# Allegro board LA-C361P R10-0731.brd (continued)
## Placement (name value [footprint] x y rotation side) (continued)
PR268  0_0402_5%  [R_0402]  28.27 101.01 180 bottom
PR269  100K_0402_5%  [R_0402]  29.68 1.71 180 top
PR270  0_0402_5%  [R_0402]  9.27 16.65 0 bottom
PR271  100K_0402_1%  [R_0402]  29.41 25.15 180 top
PR272  100K_0402_1%  [R_0402]  29.34 24.25 270 top
PR273  16.5K_0402_1%  [R_0402]  17.65 20.07 0 bottom
PR274  100K_0402_1%  [R_0402]  23.31 10.22 90 top
PR275  100K_0402_1%  [R_0402]  34.6 31.94 0 top
PR276  2K_0402_1%  [R_0402]  34.57 33.85 180 top
PR277  0_0402_5%  [R_0402]  31.1 30.07 270 top
PR278  100K_0402_1%  [R_0402]  18.09 22.49 0 top
PR279  0_0402_5%  [R_0402]  19 23.5 180 top
PR280  0_0402_5%  [R_0402]  19.89 8.39 180 top
PR281  0_0402_5%  [R_0402]  33.71 32.42 270 top
PR282  100K_0402_5%  [R_0402]  10.21 11.57 0 top
PR283  100K_0402_5%  [R_0402]  8.5 10.04 0 top
PR287  0_0402_5%  [R_0402]  20.26 2.63 270 top
PR290  0_0402_5%  [R_0402]  20.31 30.36 0 bottom
PR291  0_0402_5%  [R_0402]  23 30.36 180 bottom
PR292  100K_0402_5%  [R_0402]  17.92 1.66 180 top
PR299  100K_0402_5%  [R_0402]  28.45 6.35 90 top
PR300  0.01_1206_1%  [R_1206_4P-D]  55.02 9.1 270 bottom
PR301  0_0402_5%  [R0402_0OHM]  52.57 11.1 90 top
PR302  0_0402_5%  [R0402_0OHM]  51.69 11.1 90 top
PR303  4.02K_0402_1%  [R_0402]  54.17 11.76 90 top
PR304  10_1206_5%  [R_1206]  51.12 15.06 270 bottom
PR305  294K_0402_1%  [R_0402]  55.77 12.67 270 bottom
PR306  0_0402_5%  [R0402_0OHM]  60.26 17.48 180 top
PR307  2.2_0603_5%  [R_0603]  50.8 17.53 180 top
PR308  59K_0402_1%  [R_0402]  55.88 14.54 90 bottom
PR309  0_0402_5%  [R0402_0OHM]  60.26 18.37 180 top
PR310  0.01_2512_1%  [R_2512_4P]  40.92 23.57 90 bottom
PR311  100K_0402_1%  [R_0402]  54.9 11.76 90 bottom
PR312  0_0402_5%  [R0402_0OHM]  54.04 11.76 90 bottom
PR313  4.7_1206_5%  [R_1206]  33.08 4.14 0 top
PR314  0_0402_5%  [R0402_0OHM]  56.9 11.76 90 top
PR315  100_0402_1%  [R_0402]  60.26 16.52 180 top
PR316  150K_0402_1%  [R_0402]  55.12 12.65 270 top
PR317  0_0402_5%  [R0402_0OHM]  60.28 14.74 180 top
PR318  10K_0402_1%  [R_0402]  52.39 21.34 90 top
PR319  4.02K_0402_1%  [R_0402]  55.18 21.22 90 top
PR320  10_0603_1%  [R_0603]  56.26 21.22 90 bottom
PR321  1K_0402_1%  [R_0402]  57.34 22.42 270 top
PR322  0_0402_5%  [R0402_0OHM]  58.23 22.42 270 top
PR323  121K_0402_1%  [R_0402]  56.64 19.33 270 bottom
PR324  0_0402_5%  [R0402_0OHM]  60.28 15.63 180 top
PR325  10K_0402_1%  [R_0402]  57.8 16.52 180 bottom
PR326  2.2K_0402_5%  [R_0402]  346.97 26.3 270 top
PR327  100K_0402_5%  [R_0402]  58.85 10.6 0 bottom
PR399  0_0402_5%  [R_0402]  52.77 11.74 90 bottom
PR400  0_0402_5%  [R0402_0OHM]  348.88 21.98 180 bottom
PR401  68.1K_0402_1%  [R_0402]  348.87 22.87 180 top
PR402  154K_0402_1%  [R_0402]  348.03 18.93 0 top
PR403  100K_0402_1%  [R_0402]  348.87 21.98 180 top
PR404  100K_0402_1%  [R_0402]  348.03 19.82 0 top
PR405  16.9K_0402_1%  [R_0402]  346.97 24.41 270 top
PR406  10.2K_0402_1%  [R_0402]  348.03 18.04 0 top
PR407  0_0402_5%  [R0402_0OHM]  345.12 24.41 270 top
PR408  0_0402_5%  [R0402_0OHM]  346.08 24.41 270 top
PR409  0_0402_5%  [R0402_0OHM]  347.98 17.14 90 bottom
PR410  200_0402_1%  [R_0402]  348.03 17.09 0 top
PR411  2.2_0603_5%  [R_0603]  342.27 24.08 0 top
PR412  2.2_0603_5%  [R_0603]  341.89 17.22 0 top
PR413  4.7_1206_5%  [R_1206]  337.69 29.47 90 top
PR414  4.7_1206_5%  [R_1206]  339.28 10.68 90 top
PR415  0_0402_5%  [R0402_0OHM]  340.58 21.97 180 top
PR428  100K_0402_1%  [R_0402]  345.12 24.41 270 bottom
PR500  0_0402_5%  [R0402_0OHM]  130.65 3.2 270 bottom
PR501  1M_0402_1%  [R_0402]  130.68 3.18 270 top
PR502  4.7_1206_5%  [R_1206]  126.68 8.33 0 bottom
PR503  0_0402_5%  [R0402_0OHM]  133.87 5.98 180 top
PR504  90.9K_0402_1%  [R_0402]  134.76 2.16 90 top
PR508  133K_0402_1%  [R_0402]  135.68 3.06 270 top
PR510  0_0402_5%  [R_0402]  132.46 2.26 90 top
PR512  0_0402_5%  [R_0402]  133.33 2.97 270 bottom
PR600  2.2_0603_5%  [R_0603]  283.15 28.65 0 bottom
PR601  3.57K_0402_1%  [R_0402]  288.99 26.49 180 bottom
PR602  4.7_1206_5%  [R_1206]  269.43 26.87 180 bottom
PR603  5.1_0603_5%  [R_0603]  289.54 25.23 90 top
PR604  16.2K_0402_1%  [R_0402]  291.85 31.19 90 top
PR605  1M_0402_1%  [R_0402]  292.75 27.19 180 bottom
PR606  0_0402_5%  [R0402_0OHM]  292.75 28.46 180 bottom
PR607  27K_0402_1%  [R_0402]  292.8 31.19 90 bottom
PR608  0_0402_5%  [R0402_0OHM]  292.75 29.35 180 bottom
PR609  100K_0402_5%  [R_0402]  292.75 26.3 180 bottom
PR610  0_0402_5%  [R_0402]  291.83 30.23 0 top
PR700  210K_0402_1%  [R_0402]  247.65 48.46 90 top
PR701  100K_0402_1%  [R_0402]  247.65 51.22 270 top
PR702  10_1206_5%  [R_1206]  236.91 51.96 0 top
PR703  5.1_0603_5%  [R_0603]  243.08 54.43 90 top
PR704  210K_0402_1%  [R_0402]  248.55 53.13 180 top
PR705  0_0402_5%  [R0402_0OHM]  248.55 52.16 180 top
PR800  0_0402_5%  [R0402_0OHM]  109.92 64.51 90 bottom
PR801  1M_0402_1%  [R_0402]  109.03 64.51 90 bottom
PR802  4.7_1206_5%  [R_1206]  114.17 57.67 180 bottom
PR803  0_0603_5%  [R0603_0OHM]  107.19 62.11 270 top
PR804  36.5K_0402_1%  [R_0402]  107.13 64.51 90 bottom
PR806  62K_0402_1%  [R_0402]  105.28 64.51 90 top
PR808  0_0402_5%  [R0402_0OHM]  171.69 70.68 270 top
PR809  0_0402_5%  [R0402_0OHM]  170.74 70.68 270 top
PR810  100_0402_1%  [R_0402]  170.74 72.46 270 top
PR811  0_0402_5%  [R_0402]  108.08 65.43 270 bottom
PR812  0_0402_5%  [R0402_0OHM]  107.13 64.51 90 top
PR813  100_0402_1%  [R_0402]  171.69 72.46 270 top
PR900  0_0402_5%  [R_0402]  221.35 53.73 0 top
PR901  1M_0402_1%  [R_0402]  220.16 54.17 90 bottom
PR902  4.7_1206_5%  [R_1206]  217.17 54.68 180 top
PR903  0_0603_5%  [R0603_0OHM]  220.09 48.33 270 top
PR904  100K_0402_1%  [R_0402]  222.26 49.92 180 top
PR905  10K_0402_5%  [R_0402]  222.26 51.95 180 top
PR906  133K_0402_1%  [R_0402]  221.35 50.81 0 top
PR907  0_0402_5%  [R0402_0OHM]  222.26 52.84 180 top
PR910  0_0402_5%  [R_0402]  216.47 48.28 270 top
PR912  0_0402_5%  [R0402_0OHM]  223.71 51.29 270 top
PR913  62K_0402_1%  [R_0402]  167.32 103.34 270 top
PR1000  0_0402_5%  [R0402_0OHM]  165.48 102.42 90 bottom
PR1001  10K_0402_1%  [R_0402]  166.37 102.42 90 bottom
PR1002  19.6K_0402_1%  [R_0402]  163.64 106.82 180 top
PR1003  2K_0402_1%  [R_0402]  163.64 105.86 180 bottom
PR1004  20K_0402_1%  [R_0402]  164.59 102.42 90 bottom
PR1005  18.2K_0402_1%  [R_0402]  163.64 104.91 180 bottom
PR1006  47K_0402_1%  [R_0402]  168.28 103.32 270 bottom
PR1007  2.2_0603_5%  [R_0603]  169.4 103.9 270 bottom
PR1008  10_1206_5%  [R_1206]  183.33 108.66 180 top
PR1009  20_0402_1%  [R_0402]  163.67 109.17 180 top
PR1010  340K_0402_1%  [R_0402]  162.75 107.77 0 bottom
PR1011  9.1K_0402_1%  [R_0402]  172.91 106.82 180 bottom
PR1012  0_0402_5%  [R0402_0OHM]  217.39 62.42 180 top
PR1013  100_0402_1%  [R_0402]  184.85 97.35 270 top
PR1014  2.2_0603_5%  [R_0603]  172.09 109.74 0 bottom
PR1015  0_0402_5%  [R0402_0OHM]  217.41 61.48 180 top
PR1016  0_0402_5%  [R_0402]  163.59 110.09 180 bottom
PR1017  100_0402_1%  [R_0402]  183.9 97.35 270 top
PR1018  15.8K_0402_1%  [R_0402]  163.59 111.9 180 top
PR1019  2.2_0603_5%  [R_0603]  169.55 111.32 90 bottom
PR1020  10K_0402_1%  [R_0402]  164.97 112.61 270 bottom
PR1021  10_1206_5%  [R_1206]  183.52 115.9 180 top
PR1022  10K_0402_1%  [R_0402]  165.86 112.61 270 bottom
PR1023  10K_0402_1%  [R_0402]  166.75 112.61 270 bottom
PR1024  1_0402_5%  [R_0402]  167.64 111.69 90 bottom
PR1025  0_0402_5%  [R0402_0OHM]  169.8 100.78 0 bottom
PR1026  2.2_0603_5%  [R_0603]  173.99 100.28 90 bottom
PR1027  10_1206_5%  [R_1206]  183.01 100.97 180 top
PR1028  47K_0402_1%  [R_0402]  168.28 103.34 270 top
PR1100  12.1K_0402_1%  [R_0402]  111.13 109.99 0 bottom
PR1101  1_0402_5%  [R_0402]  117.54 112.09 270 bottom
PR1102  0_0402_5%  [R0402_0OHM]  118.43 112.09 270 bottom
PR1103  100_0402_1%  [R_0402]  116.8 108.82 180 bottom
PR1104  95.3K_0402_1%  [R_0402]  111.13 109.04 0 bottom
PR1105  10.2K_0402_1%  [R_0402]  111.13 108.09 0 top
PR1106  27.4K_0402_1%  [R_0402]  108.78 107.2 0 bottom
PR1107  165K_0402_1%  [R_0402]  122.44 111.2 90 top
PR1108  16.9K_0402_1%  [R_0402]  121.55 111.2 90 top
PR1109  5.62K_0402_1%  [R_0402]  120.59 111.2 90 top
PR1110  110K_0402_1%  [R_0402]  119.7 111.2 90 top
PR1111  3.6K_0402_1%  [R_0402]  111.13 107.13 0 bottom
PR1112  1K_0402_1%  [R_0402]  108.83 106.24 0 top
PR1113  2.94K_0402_1%  [R_0402]  109.73 104.47 90 top
PR1114  1.91K_0402_1%  [R_0402]  113.92 112.09 270 top
PR1115  1.18K_0402_1%  [R_0402]  122.56 108.91 0 top
PR1116  48.7K_0402_1%  [R_0402]  123.31 110.82 0 top
PR1117  1K_0402_1%  [R_0402]  124.84 108.9 90 top
PR1118  0_0402_5%  [R0402_0OHM]  111.99 112.09 270 top
PR1119  0_0402_5%  [R0402_0OHM]  112.97 112.09 270 top
PR1120  11K_0402_1%  [R_0402]  123.41 109.91 180 bottom
PR1121  2.61K_0402_1%  [R_0402]  113.73 92.59 0 bottom
PR1122  2.61K_0402_1%  [R_0402]  120.31 86.43 0 bottom
PR1123  11K_0402_1%  [R_0402]  112.04 103.01 180 bottom
PR1124  2K_0402_1%  [R_0402]  123.05 107.13 0 top
PR1125  1K_0402_1%  [R_0402]  125.1 105.37 270 bottom
PR1126  2.05K_0402_1%  [R_0402]  122.56 105.29 0 bottom
PR1127  1K_0402_1%  [R_0402]  109.73 104.45 90 bottom
PR1128  2.49K_0402_1%  [R_0402]  122.56 106.24 0 bottom
PR1129  113K_0402_1%  [R_0402]  122.56 104.28 0 top
PR1130  470_0402_1%  [R_0402]  111.13 105.29 0 bottom
PR1131  45.3_0402_1%  [R_0402]  114.81 114 270 top
PR1132  0_0402_5%  [R0402_0OHM]  115.76 112.1 270 top
PR1133  390_0402_1%  [R_0402]  118.49 100.47 270 bottom
PR1134  11K_0402_1%  [R_0402]  119.86 98.28 270 bottom
PR1135  1K_0402_1%  [R_0402]  118.11 97.24 90 bottom
PR1136  2.61K_0402_1%  [R_0402]  150.11 99.96 180 bottom
PR1137  90.9K_0402_1%  [R_0402]  112.9 100.47 270 top
PR1138  27.4K_0402_1%  [R_0402]  113.67 98.69 0 top
PR1139  2K_0402_1%  [R_0402]  116.59 100.47 270 top
PR1140  1K_0402_1%  [R_0402]  117.48 100.45 270 bottom
PR1141  4.87K_0402_1%  [R_0402]  115.7 100.47 270 bottom
PR1142  2.43K_0402_1%  [R_0402]  116.59 99.55 90 bottom
PR1143  2K_0402_1%  [R_0402]  109.55 107.2 180 top
PR1144  10.2K_0402_1%  [R_0402]  114.75 99.55 90 top
PR1145  100_0402_1%  [R_0402]  116.65 114 270 top
PR1200  10_1206_5%  [R_1206]  147.77 103.39 270 top
PR1201  100K_0402_1%  [R_0402]  128.27 99.77 180 bottom
PR1202  3.65K_0603_1%  [R_0603]  129.2 99.25 0 bottom
PR1203  2.2_0402_1%  [R_0402]  127.38 98.81 0 bottom
PR1204  10_1206_5%  [R_1206]  145.03 117.23 0 bottom
PR1205  100K_0402_1%  [R_0402]  128.27 101.93 180 bottom
PR1206  3.65K_0603_1%  [R_0603]  129.2 100.5 0 bottom
PR1207  2.2_0402_1%  [R_0402]  127.38 100.97 0 bottom
PR1208  10_1206_5%  [R_1206]  160.78 107.32 90 top
PR1209  100K_0402_1%  [R_0402]  128.08 97.74 180 bottom
PR1210  3.65K_0603_1%  [R_0603]  128.98 97 0 bottom
PR1211  2.2_0402_1%  [R_0402]  127.15 96.83 0 bottom
PR1212  100K_0402_1%  [R_0402]  125.73 99.77 180 bottom
PR1213  100K_0402_1%  [R_0402]  125.73 98.81 180 bottom
PR1214  100K_0402_1%  [R_0402]  125.73 101.67 180 bottom
PR1215  100K_0402_1%  [R_0402]  125.73 100.72 180 bottom
PR1216  100K_0402_1%  [R_0402]  125.68 96.66 180 bottom
PR1217  100K_0402_1%  [R_0402]  125.67 97.54 180 bottom
PR1218  0_0402_5%  [R0402_0OHM_NPM]  147.45 105.16 0 bottom
PR1219  0_0402_5%  [R0402_0OHM_NPM]  151.51 105.16 180 bottom
PR1220  0_0402_5%  [R0402_0OHM_NPM]  147.45 112.59 0 bottom
PR1221  0_0402_5%  [R0402_0OHM_NPM]  151.51 112.59 180 bottom
PR1222  0_0402_5%  [R0402_0OHM_NPM]  158.18 107.64 270 bottom
PR1223  0_0402_5%  [R0402_0OHM_NPM]  158.18 103.64 90 bottom
PR1224  2.2_0402_1%  [R_0402]  137.54 110.19 270 bottom
PR1225  2.2_0402_1%  [R_0402]  137.67 115.66 270 bottom
PR1226  2.2_0402_1%  [R_0402]  157.3 118.88 180 bottom
PR1300  4.7_1206_5%  [R_1206]  111.63 81.29 270 top
PR1301  3.65K_0603_1%  [R_0603]  105.92 101.99 90 top
PR1302  2.2_0402_1%  [R_0402]  109.22 102.83 270 top
PR1303  100K_0402_1%  [R_0402]  105.98 102.18 90 bottom
PR1304  2.2_0402_1%  [R_0402]  108.27 101.91 90 top
PR1305  3.65K_0603_1%  [R_0603]  107.19 101.99 90 top
PR1306  100K_0402_1%  [R_0402]  107.19 102.18 90 bottom
PR1307  4.7_1206_5%  [R_1206]  112.02 69.41 90 top
PR1308  4.7_1206_5%  [R_1206]  105.6 87.19 90 bottom
PR1309  3.65K_0603_1%  [R_0603]  126.62 104.21 90 top
PR1310  0_0402_5%  [R0402_0OHM]  127.7 104.25 90 top
PR1311  0_0402_5%  [R0402_0OHM]  115.51 95.25 90 top
PR1312  0_0402_5%  [R0402_0OHM_NPM]  113.98 82.56 0 bottom
PR1313  0_0402_5%  [R0402_0OHM_NPM]  118.05 82.56 180 bottom
PR1314  0_0402_5%  [R0402_0OHM_NPM]  113.08 70.37 0 bottom
PR1315  0_0402_5%  [R0402_0OHM_NPM]  117.16 70.37 180 bottom
PR1316  0_0402_5%  [R0402_0OHM_NPM]  109.09 88.71 0 bottom
PR1317  0_0402_5%  [R0402_0OHM_NPM]  112.65 88.71 180 bottom
PR1318  10_0402_1%  [R_0402]  116.65 112.1 270 top
PR1319  49.9_0402_1%  [R_0402]  114.81 112.1 270 top
PR1320  2.2_0402_1%  [R_0402]  104.14 81.49 270 bottom
PR1321  2.2_0402_1%  [R_0402]  103.63 77.17 270 bottom
PU200  -  [INA199A1DCKR_SC70-6]  18.04 52.21 180 bottom
PU201  -  [LM393DMR2G_MICRO8]  28.13 29.03 270 bottom
PU202  -  [LM393DMR2G_MICRO8]  16.07 21.6 270 bottom
PU203  -  [RT9069-33GB_SOT23-5]  28.63 20.34 90 top
PU204  -  [MC74VHC1G08DFT2G_SC70-5]  7.31 12.41 270 top
PU300  BQ24777RUYR_WQFN28_4x4  [BQ24777RUYR_WQFN28_4X4]  53.91 15.06 90 top
PU400  -  [TPS51285BRUKR_QFN20_3X3]  345.89 19.5 90 top
PU500  -  [SYX196DQNC_QFN10_3X3]  131.53 4.5 0 bottom
PU600  -  [G5616ARZ1U_TQFN20_3X3]  287.47 31.12 0 bottom
PU700  -  [TPS51367RVER_QFN28_4P5X3P5]  245.19 52.74 180 top
PU800  -  [SYX196DQNC_QFN10_3X3]  109.41 62.75 180 bottom
PU900  -  [SYX196DQNC_QFN10_3X3]  219.47 52.7 270 top
PU1000  -  [RT8813AGQW_WQFN24_4X4]  168.97 105.67 180 bottom
PU1001  RT9610BZQW_WDFN8_2X2~D  [RT9610BZQW_WDFN8_2X2]  172.28 98.56 0 bottom
PU1100  ISL95829HRTZ-T_TQFN48_6X6  [ISL95855HRTZ-T_TQFN48_6X6]  114.17 108.09 0 top
PU1200  -  [AOZ5019QI_QFN23_5X3P5]  138.84 107.96 90 bottom
PU1201  -  [AOZ5019QI_QFN23_5X3P5]  138.9 114.38 90 bottom
PU1202  -  [AOZ5019QI_QFN23_5X3P5]  156.16 117.46 0 bottom
PU1300  -  [AOZ5019QI_QFN23_5X3P5]  105.35 80.08 90 bottom
PU1301  -  [AOZ5019QI_QFN23_5X3P5]  104.59 72.46 90 bottom
PU1302  -  [ISL95808HRZ-TS2378_DFN8_2X2]  115.78 95.18 270 bottom
QE2  -  [DMN65D8LDW-7_SOT363-6]  226.62 13.03 0 top
QE4  -  [DMN65D8LDW-7_SOT363-6]  311.67 16.07 180 top
QE5  -  [MMBT3904WH_SOT323-3]  163.54 119.13 270 bottom
QE6  -  [MMBT3904WH_SOT323-3]  182.49 77.95 0 top
QE7  -  [MMBT3904WH_SOT323-3]  113.59 114.8 270 bottom
QE8  -  [MMBT3904WH_SOT323-3]  179.2 48.64 180 bottom
QE9  -  [MMBT3904WH_SOT323-3]  239.85 115.26 90 bottom
QE10  -  [MMBT3904WH_SOT323-3]  308.95 19.44 90 top
QE11  -  [MMBT3904WH_SOT323-3]  27.24 54.95 0 top
QE12  -  [MMBT3904WH_SOT323-3]  281.43 28.11 180 bottom
QE13  -  [L2N7002WT1G_SC-70-3]  218.95 9.41 180 top
QE15  -  [MMBT3904WH_SOT323-3]  158.67 69.33 180 top
QE17  -  [DMG2301U-7_SOT23-3]  163.42 4.39 90 top
QE18  -  [DMN65D8LDW-7_SOT363-6]  68.34 17.6 180 bottom
QE19  -  [DMN65D8LDW-7_SOT363-6]  223.63 13.16 0 top
QF1  -  [DMN65D8LDW-7_SOT363-6]  226.64 50.19 270 top
QH4  -  [DMN65D8LDW-7_SOT363-6]  72.2 6.37 270 top
QR1  -  [L2N7002WT1G_SC-70-3]  332.61 43.32 90 bottom
QT1  -  [DMN65D8LDW-7_SOT363-6]  9.34 43.46 270 top
QV9  -  [L2N7002WT1G_SC-70-3]  56.9 27.06 0 top
QV11  SI3457BDV-T1-E3_TSOP6~D  [SI3457BDV-T1-E3_TSOP6]  50.24 25.2 270 bottom
QV12  -  [L2N7002WT1G_SC-70-3]  52.45 22.11 0 bottom
QV13  -  [L2N7002WT1G_SC-70-3]  22.79 77.99 270 top
QV14  -  [L2N7002WT1G_SC-70-3]  17.51 90.03 180 bottom
QV21  -  [DMN65D8LDW-7_SOT363-6]  207.2 60.35 270 bottom
QV22  -  [L2N7002WT1G_SC-70-3]  230.13 100.21 90 top
QV23  -  [L2N7002WT1G_SC-70-3]  210.95 110.88 180 top
QV24  -  [L2N7002WT1G_SC-70-3]  245.24 63.74 90 top
QV25  -  [L2N7002WT1G_SC-70-3]  247.65 82.3 0 top
QV39  -  [L2N7002WT1G_SC-70-3]  197.66 57.12 0 top
QV86  -  [DMG2301U-7_SOT23-3]  201.65 55.76 90 bottom
QV87  -  [L2N7002WT1G_SC-70-3]  198.89 59.7 270 bottom
QV88  -  [L2N7002WT1G_SC-70-3]  209.74 50.55 270 top
QV89  -  [L2N7002WT1G_SC-70-3]  18.54 26.81 270 top
QX1  -  [DMN65D8LDW-7_SOT363-6]  15.69 91.56 90 bottom
QZ6  -  [DMN65D8LDW-7_SOT363-6]  237.25 103.45 180 top
QZ7  -  [DMN65D8LDW-7_SOT363-6]  202 54.38 270 top
QZ8  -  [L2N7002WT1G_SC-70-3]  239.84 105.29 270 top
QZ9  -  [DMG2301U-7_SOT23-3]  41.7 24.56 90 top
RD1  0_0402_5%  [R_0402]  171.84 18.78 0 top
RD2  0_0402_5%  [R_0402]  173.6 24.17 0 top
RD3  0_0402_5%  [R_0402]  152.08 18.56 270 top
RD4  0_0402_5%  [R_0402]  248.51 18.44 270 top
RD5  0_0402_5%  [R0402_0OHM]  249.77 24.22 270 top
RD6  0_0402_5%  [R_0402]  228.38 18.56 270 top
RD7  10K_0402_5%  [R_0402]  268.43 13.34 180 top
RD8  10K_0402_5%  [R_0402]  267.51 9.28 0 top
RD9  0_0402_5%  [R_0402]  268.43 6.36 180 top
RD10  10K_0402_5%  [R_0402]  256.27 3.82 0 bottom
RD28  0_0402_5%  [R0402_0OHM]  172.76 17.89 180 top
RD29  0_0402_5%  [R0402_0OHM]  176.12 23.22 0 top
RD30  0_0402_5%  [R0402_0OHM]  151.19 17.65 90 top
RD31  0_0402_5%  [R0402_0OHM]  134.24 17.81 90 top
RD35  470_0402_1%  [R_0402]  132.34 17.81 90 top
RD38  0_0402_5%  [R0402_0OHM]  247.62 17.52 90 top
RD39  0_0402_5%  [R_0402]  250.66 23.31 90 top
RD40  0_0402_5%  [R0402_0OHM]  227.49 17.65 90 top
RD58  0_0402_5%  [R0402_0OHM]  254.5 3.82 0 bottom
RD59  0_0402_5%  [R_0402]  267.51 8.33 0 top
RE3  300_0402_5%  [R_0402]  324.92 117.61 0 top
RE7  2.4K_0402_5%  [R_0402]  222.64 12.23 180 top
RE9  2.4K_0402_5%  [R_0402]  221.18 13.85 180 top
RE11  33_0402_5%  [R_0402]  150.19 7.71 90 top
RE13  10K_0402_5%  [R_0402]  158.29 7.95 0 top
RE14  4.7K_0402_5%  [R_0402]  159.21 6.93 180 top
RE15  47K_0402_5%  [R_0402]  348.95 117.61 180 top
RE16  0_0402_5%  [R0402_0OHM]  290.32 11.87 90 top
RE17  2.2K_0402_5%  [R_0402]  290.25 16.77 0 top
RE18  2.2K_0402_5%  [R_0402]  290.25 15.88 0 top
RE19  10K_0402_5%  [R_0402]  300.86 3.82 0 top
RE20  2.2K_0402_5%  [R_0402]  296.04 7.45 270 top
RE21  2.2K_0402_5%  [R_0402]  295.4 4.12 90 top
RE22  10K_0402_5%  [R_0402]  294.9 23.3 90 top
RE23  10K_0402_5%  [R_0402]  290.22 21.03 270 top
RE24  4.7K_0402_5%  [R_0402]  301.88 24.22 270 top
RE25  10K_0402_5%  [R_0402]  295.11 7.45 270 top
RE26  4.7K_0402_5%  [R_0402]  300.99 24.22 270 top
RE27  10K_0402_5%  [R_0402]  299.39 28.08 0 top
RE30  100K_0402_5%  [R_0402]  298.45 5.04 270 top
RE31  10K_0402_5%  [R_0402]  310.44 17.66 0 top
RE32  100K_0402_5%  [R_0402]  300.99 26.5 270 top
RE33  10K_0402_5%  [R_0402]  301.88 26.5 270 top
RE34  100K_0402_5%  [R_0402]  292.48 4.12 90 top
RE35  0_0402_5%  [R_0402]  303.28 24.22 270 top
RE36  1K_0402_5%  [R_0402]  283.97 3.74 90 top
RE37  0_0402_5%  [R0402_0OHM]  302.77 25.59 90 top
RE38  0_0402_5%  [R_0402]  297.56 5.04 270 top
RE39  0_0402_5%  [R0402_0OHM]  297.82 6.54 90 top
RE41  100K_0402_5%  [R_0402]  308.1 10.98 90 top
RE43  1K_0402_5%  [R_0402]  287.91 15.81 90 top
RE44  100K_0402_5%  [R_0402]  288.93 15.81 90 top
RE45  10_0402_5%  [R_0402]  307.21 10.98 90 top
RE48  33_0402_5%  [R_0402]  293.12 23.3 90 top
RE50  100K_0402_5%  [R_0402]  287.53 14.94 270 top
RE51  0_0402_5%  [R0402_0OHM]  291.16 10.55 180 top
RE52  10K_0402_5%  [R_0402]  309.25 13.9 90 top
RE54  10K_0402_5%  [R_0402]  286.64 14.03 90 top
RE55  4.7K_0402_5%  [R_0402]  287.61 18.06 180 top
RE56  100K_0402_5%  [R_0402]  310.11 12.77 0 top
RE57  1K_0402_5%  [R_0402]  309.07 16.14 180 top
RE58  1.33K_0402_1%  [R_0402]  306.3 9.19 0 top
RE59  100K_0402_5%  [R_0402]  298.02 26.68 180 top
RE60  49.9_0402_1%  [R_0402]  312.99 27.75 90 top
RE61  100_0402_1%  [R_0402]  297.1 24.39 0 top
RE62  10_0402_5%  [R_0402]  306.38 17.66 0 top
RE63  10K_0402_5%  [R_0402]  309.06 27.75 90 top
RE64  10K_0402_5%  [R_0402]  307.02 27.75 90 top
RE65  100K_0402_5%  [R_0402]  308.17 27.75 90 top
RE66  8.2K_0402_5%  [R_0402]  307.34 18.98 90 top
RE67  1K_0402_5%  [R_0402]  300.56 7.37 180 top
RE68  10K_0402_5%  [R_0402]  287.66 7.93 90 top
RE69  2.2K_0402_5%  [R_0402]  311.66 19.9 270 top
RE70  10K_0402_5%  [R_0402]  285.87 8.84 0 top
RE71  100K_0402_5%  [R_0402]  272.21 16.26 0 top
RE72  100K_0402_5%  [R_0402]  272.21 15.25 0 top
RE73  10K_0402_5%  [R_0402]  283.54 13.72 180 top
RE74  10K_0402_5%  [R_0402]  283.54 14.74 180 top
RE75  10K_0402_5%  [R_0402]  283.54 15.76 180 top
RE76  10K_0402_5%  [R_0402]  283.54 16.9 180 top
RE77  4.7K_0402_5%  [R_0402]  154.23 2.93 0 top
RE81  100K_0402_5%  [R_0402]  101.28 35.72 270 top
RE82  10K_0402_5%  [R_0402]  98.17 34.06 90 top
RE83  100K_0402_5%  [R_0402]  321.57 37.4 90 top
RE84  10K_0402_5%  [R_0402]  321.57 40.15 270 top
RE85  10K_0402_5%  [R_0402]  152.45 2.99 0 top
RE86  10K_0402_5%  [R_0402]  149.14 11.36 0 top
RE87  100K_0402_5%  [R_0402]  219.41 12.45 180 top
RE89  10K_0402_5%  [R_0402]  290.7 5.04 270 top
RE90  100K_0402_5%  [R_0402]  291.59 4.12 90 top
RE93  0_0603_5%  [R0603_0OHM]  222.06 11.18 180 top
RE94  2.2K_0402_5%  [R_0402]  298.64 30.67 90 top
RE95  2.2K_0402_5%  [R_0402]  296.28 32.46 0 top
RE96  100_0402_5%  [R_0402]  295.78 23.3 90 top
RE99  10K_0402_5%  [R_0402]  299.09 25.59 90 top
RE100  10K_0402_5%  [R_0402]  98.08 32.95 0 top
RE101  10K_0402_5%  [R_0402]  320.49 39.24 90 top
RE102  0_0402_5%  [R0402_0OHM]  299.98 26.5 270 top
RE103  0_0402_5%  [R0402_0OHM]  304.42 28.91 270 top
RE104  0_0603_5%  [R0603_0OHM]  97.03 34.07 90 top
RE105  0_0603_5%  [R0603_0OHM]  320.8 41.91 0 top
RE107  0_0402_5%  [R0402_0OHM]  291.16 21.04 270 top
RE108  0_0402_5%  [R0402_0OHM]  296.93 6.54 90 top
RE109  0_0402_5%  [R0402_0OHM]  296.38 5.05 270 top
RE110  10K_0402_5%  [R_0402]  282.58 4.71 270 top
RE111  43K_0402_1%  [R_0402]  292.18 23.33 90 top
RE112  0_0402_5%  [R0402_0OHM]  299.4 5.04 270 top
RE113  33_0402_5%  [R_0402]  151.19 2.42 90 top
RE114  33_0402_5%  [R_0402]  149.28 6.65 0 top
RE115  33_0402_5%  [R_0402]  149.29 8.63 270 top
RE116  0_0402_5%  [R0402_0OHM]  153.47 8.15 0 bottom
RE117  0_0402_5%  [R0402_0OHM]  152.59 11.45 0 bottom
RE118  0_0402_5%  [R0402_0OHM]  299.98 24.22 270 top
RE119  0_0402_5%  [R0402_0OHM]  303.53 28.91 270 top
RE120  0_0402_5%  [R0402_0OHM]  303.61 3.82 180 top
RE121  0_0603_5%  [R0603_0OHM]  148.97 13.66 270 top
RE122  0_0402_5%  [R0402_0OHM]  300.15 30.11 0 top
RE125  0_0402_5%  [R0402_0OHM]  156.92 2.93 180 top
RE126  0_0402_5%  [R_0402]  155.53 11.31 180 top
RE127  10K_0402_5%  [R_0402]  158.29 5.98 0 top
RE128  0_0402_5%  [R_0402]  156.77 11.57 0 top
RE129  0_0402_5%  [R0402_0OHM]  159.46 11.57 180 top
RE132  100_0402_5%  [R_0402]  162.31 8.01 270 top
RE133  0_0402_5%  [R0402_0OHM]  148.34 8.59 270 top
RE134  10K_0402_5%  [R_0402]  155.53 12.2 180 top
RE136  5.1K_0402_1%  [R_0402]  67.9 20.46 180 bottom
RE137  5.1K_0402_1%  [R_0402]  67.74 16.65 0 bottom
RE138  0_0402_5%  [R0402_0OHM]  306.02 25.66 180 top
RE139  0_0402_5%  [R0402_0OHM]  300.86 4.76 90 top
RE140  10K_0402_5%  [R_0402]  285.87 7.95 0 top
RE141  0_0603_5%  [R0603_0OHM]  152.15 5.09 0 bottom
RF1  0_0603_5%  [R0603_0OHM]  234.29 50.95 90 top
RF2  100K_0402_5%  [R_0402]  227.39 52.21 0 top
RF3  100K_0402_5%  [R_0402]  231.08 50.89 270 top
RF4  100K_0402_5%  [R_0402]  230.98 52.21 180 top
RF5  100K_0402_5%  [R_0402]  231.97 50.89 270 top
RH2  1K_0402_5%  [R_0402]  132.92 94.56 180 bottom
RH5  1K_0402_5%  [R_0402]  123.57 94.55 90 bottom
RH6  0_0402_5%  [R_0402]  132 95.45 0 bottom
RH8  0_0402_5%  [R0402_0OHM]  124.46 95.46 270 bottom
RH12  0_0402_5%  [R0402_0OHM]  119.19 95.4 270 bottom
RH24  24.9_0402_1%  [R_0402]  173.79 54.87 0 bottom
RH30  24.9_0402_1%  [R_0402]  177.14 86.39 90 top
RH57  49.9_0402_1%  [R_0402]  131.79 75.92 0 bottom
RH58  49.9_0402_1%  [R_0402]  131.79 77.7 0 bottom
RH59  49.9_0402_1%  [R_0402]  132.7 76.81 180 bottom
RH67  1.3K_0402_5%  [R_0402]  332.21 79.55 180 top
RH70  10M_0402_5%  [R_0402]  97.92 2.69 270 top
RH71  2.7K_0402_1%  [R_0402]  102.68 23.05 90 bottom
RH72  1M_0402_5%  [R_0402]  102.15 26.82 270 top
RH74  3.3K_0402_5%  [R_0402]  68.33 11.52 270 bottom
RH75  1K_0402_5%  [R_0402]  79.57 2.74 0 top
RH77  100K_0402_5%  [R_0402]  60.68 10.82 0 top
RH78  1K_0402_5%  [R_0402]  73.2 2.17 0 top
RH82  4.7K_0402_5%  [R_0402]  73.2 3.12 0 top
RH83  20K_0402_5%  [R_0402]  94.11 4.33 180 top
RH84  20K_0402_5%  [R_0402]  96.2 4.34 0 top
RH85  8.2K_0402_5%  [R_0402]  106.11 7.26 270 top
RH88  47K_0402_5%  [R_0402]  95.73 8.54 180 top
RH91  100K_0402_5%  [R_0402]  105.67 2.47 90 bottom
RH95  51_0402_5%  [R_0402]  103.33 9.15 180 top
RH96  0_0402_5%  [R0402_0OHM]  109.93 3.44 180 top
RH97  51_0402_5%  [R_0402]  108.85 9.27 180 top
RH98  51_0402_5%  [R_0402]  109.72 9.27 0 top
RH100  51_0402_5%  [R_0402]  108.66 7.63 180 bottom
RH108  100_0402_1%  [R_0402]  90.78 28.81 180 bottom
RH109  113_0402_1%  [R_0402]  101.87 14.41 0 bottom
RH110  10K_0402_5%  [R_0402]  76.02 12.58 180 top
RH111  10K_0402_5%  [R_0402]  67.17 10.58 0 top
RH119  4.7K_0402_5%  [R_0402]  68.66 14.23 180 top
RH120  4.7K_0402_5%  [R_0402]  70.94 10.66 180 bottom
RH130  4.7K_0402_5%  [R_0402]  84.71 11.07 270 top
RH133  0_0402_5%  [R0402_0OHM]  96.28 10.49 180 top
RH136  0_0603_5%  [R0603_0OHM]  79.44 4.2 180 top
RH137  0_0603_5%  [R0603_0OHM]  83.44 4.2 0 top
RH145  20_0402_5%  [R_0402]  180.54 80.07 0 bottom
RH146  30_0402_5%  [R_0402]  108.18 11.52 180 bottom
RH147  30_0402_5%  [R_0402]  108.37 10.36 180 bottom
RH148  121_0402_1%  [R_0402]  173.79 55.76 0 bottom
RH149  75_0402_1%  [R_0402]  173.79 56.65 0 bottom
RH150  100_0402_1%  [R_0402]  171.58 55.51 0 bottom
RH151  100_0402_5%  [R_0402]  132.8 103.01 270 top
RH152  56.2_0402_1%  [R_0402]  132.8 103.88 90 top
RH153  220_0402_5%  [R_0402]  133.69 104.8 270 top
RH154  60.4_0402_1%  [R_0402]  178.04 66.59 90 top
RH155  20_0402_5%  [R_0402]  130.15 82.94 0 bottom
RH156  51_0402_5%  [R_0402]  131.56 78.8 90 bottom
RH158  499_0402_1%  [R_0402]  130.15 80.84 0 bottom
RH163  1K_0402_5%  [R_0402]  173.03 81.53 180 top
RH164  1K_0402_5%  [R_0402]  179.75 64.77 90 top
RH165  1K_0402_5%  [R_0402]  129.78 78.8 90 bottom
RH166  49.9_0402_1%  [R_0402]  132.49 79.16 0 bottom
RH167  30_0402_5%  [R_0402]  182.96 62.09 90 top
RH168  22_0402_5%  [R_0402]  105.21 4.58 0 bottom
RH183  1K_0402_5%  [R_0402]  131.93 76.74 90 top
RH184  1K_0402_5%  [R_0402]  132.79 77.29 90 top
RH185  1K_0402_5%  [R_0402]  134.14 74.79 180 top
RH186  1K_0402_5%  [R_0402]  132.93 71.12 180 top
RH187  1K_0402_5%  [R_0402]  132.06 73.9 90 top
RH188  1K_0402_5%  [R_0402]  134.39 73.1 180 top
RH189  30_0402_5%  [R_0402]  104.75 13.48 90 bottom
RH190  0_0402_5%  [R0402_0OHM]  132.94 83.57 0 bottom
RH191  620_0402_5%  [R_0402]  103.66 14.26 90 bottom
RH192  30_0402_5%  [R_0402]  178.64 75.9 180 top
RH196  0_0402_5%  [R_0402]  87.9 10.79 270 top
RH197  100_0402_1%  [R_0402]  157.49 93.07 180 bottom
RH198  0_0402_5%  [R0402_0OHM]  155.65 93.07 180 bottom
RH201  100_0402_1%  [R_0402]  178.14 90.48 270 bottom
RH202  0_0402_5%  [R0402_0OHM]  178.14 91.72 90 bottom
RH203  100_0402_1%  [R_0402]  157.49 88.81 180 bottom
RH204  0_0402_5%  [R0402_0OHM]  155.65 88.81 180 bottom
RH206  1K_0402_1%  [R_0402]  124.74 17.41 90 top
RH207  1K_0402_1%  [R_0402]  233.15 19.39 270 top
RH209  1K_0402_1%  [R_0402]  123.81 18.32 270 top
RH210  1K_0402_1%  [R_0402]  233.15 17.61 270 top
RH211  24.9_0402_1%  [R_0402]  121.1 18.32 90 top
RH212  24.9_0402_1%  [R_0402]  231.42 17.42 270 top
RH309  0_0402_5%  [R0402_0OHM]  100.41 9.81 180 top
RH383  10K_0402_5%  [R_0402]  75.11 9.91 0 top
RH401  100K_0402_5%  [R_0402]  98.87 8.64 270 top
RH423  100K_0402_5%  [R_0402]  61.48 3.5 180 top
RH424  5.1K_0402_1%  [R_0402]  71.87 8.84 0 top
RH425  5.1K_0402_1%  [R_0402]  71.87 9.72 0 top
RH428  22_0402_5%  [R_0402]  105.46 5.47 0 bottom
RH453  1K_0402_5%  [R_0402]  109.02 4.33 0 top
RH454  1K_0402_5%  [R_0402]  115.77 5.52 180 top
RH455  1K_0402_5%  [R_0402]  77.28 2.27 180 top
RH456  0_0402_5%  [R_0402]  181.31 87.68 90 bottom
RH458  1K_0402_5%  [R_0402]  76.34 6.77 180 top
RH459  1K_0402_5%  [R_0402]  70.92 4.63 90 top
RH460  1K_0402_5%  [R_0402]  79.24 7.63 180 top
RH461  1K_0402_5%  [R_0402]  77.47 6.16 90 top
RH462  1K_0402_5%  [R_0402]  75.44 5.93 270 top
RH463  1K_0402_5%  [R_0402]  71.58 7.57 180 top
RH465  0_0402_5%  [R0402_0OHM]  155.65 91.61 180 bottom
RH466  100_0402_1%  [R_0402]  156.57 91.61 0 bottom
RH469  100_0402_1%  [R_0402]  176.86 90.48 270 bottom
RH470  0_0402_5%  [R0402_0OHM]  176.86 91.72 90 bottom
RH471  0_0402_5%  [R0402_0OHM]  155.65 90.27 180 bottom
RH472  100_0402_1%  [R_0402]  156.58 90.27 0 bottom
RH473  0_0402_5%  [R0402_0OHM]  164.13 68.16 270 top
RH474  1K_0402_5%  [R_0402]  130.15 84.84 0 bottom
RH475  0_0402_5%  [R_0402]  128.83 84.79 270 bottom
RH477  0_0402_5%  [R0402_0OHM]  118.3 95.4 270 bottom
RH478  0_0402_5%  [R0402_0OHM]  120.14 95.4 270 bottom
RH479  0_0402_5%  [R_0402]  119.19 94.38 180 top
RH480  1K_0402_5%  [R_0402]  119.19 93.49 180 top
RH481  1K_0402_5%  [R_0402]  130.47 92.74 270 top
RH482  1K_0402_5%  [R_0402]  130.47 90.05 90 top
RH483  150_0402_5%  [R_0402]  130.46 98.21 270 top
RH484  2_0402_1%  [R_0402]  122.89 19.24 270 top
RH485  2_0402_1%  [R_0402]  232.2 19.39 270 top
RH487  0_0402_5%  [R0402_0OHM]  116.7 5.52 0 top
RH488  1K_0402_5%  [R_0402]  130.47 96.43 270 top
RH489  1K_0402_5%  [R_0402]  70.52 3.45 0 bottom
RH490  0_0402_5%  [R_0402]  127.69 93.8 0 bottom
RH491  0_0402_5%  [R0402_0OHM]  131.89 102.09 90 top
RH492  2.2K_0402_5%  [R_0402]  119.19 95.4 180 top
RH493  2.2K_0402_5%  [R_0402]  127.69 94.71 0 bottom
RH494  51_0402_5%  [R_0402]  131.7 97.75 270 bottom
RH495  51_0402_5%  [R_0402]  134.62 97.75 270 bottom
RH496  51_0402_5%  [R_0402]  133.67 97.75 270 bottom
RH497  51_0402_5%  [R_0402]  130.15 81.92 0 bottom
RH498  51_0402_5%  [R_0402]  131.89 104.8 270 top
RH501  499_0402_1%  [R_0402]  70.54 7.77 0 bottom
RH502  499_0402_1%  [R_0402]  70.54 6.88 0 bottom
RH503  4.7K_0402_5%  [R_0402]  81.6 7.73 0 top
RH504  150K_0402_5%  [R_0402]  85.61 11.07 270 top
RH505  4.7K_0402_5%  [R_0402]  81.71 4.63 90 top
RH506  1M_0402_5%  [R_0402]  74.12 4.01 180 top
RH508  10K_0402_5%  [R_0402]  76.02 13.47 180 top
RH510  10K_0402_5%  [R_0402]  72.78 13.15 180 bottom
RH511  10K_0402_5%  [R_0402]  72.09 20.2 180 bottom
RH512  10K_0402_5%  [R_0402]  70.88 14.17 180 bottom
RH513  10K_0402_5%  [R_0402]  76.02 11.69 180 top
RH515  8.2K_0402_5%  [R_0402]  109.02 2.55 0 bottom
RH516  10K_0402_5%  [R_0402]  75.11 10.8 0 top
RH518  10K_0402_5%  [R_0402]  93.14 11.88 0 top
RH519  0_0402_5%  [R_0402]  130.15 83.96 0 bottom
RH520  100K_0402_5%  [R_0402]  75.11 9.03 0 top
RH521  0_0402_5%  [R_0402]  71.87 8.71 0 bottom
RH522  0_0402_5%  [R_0402]  71.87 9.6 0 bottom
RH523  10K_0402_5%  [R_0402]  71.87 10.61 0 bottom
RH524  4.7K_0402_5%  [R_0402]  82.36 3.51 270 top
RH525  220K_0402_5%  [R_0402]  121.36 54.24 180 top
RH527  10K_0402_5%  [R_0402]  82.82 17.92 180 top
RH528  10K_0402_5%  [R_0402]  83.74 17.92 0 top
RH529  100K_0402_5%  [R_0402]  108.71 7.64 270 top
RH530  0_0402_5%  [R_0402]  165.85 67.24 90 top
RH531  330K_0402_5%  [R_0402]  95.25 4.07 90 top
RH533  8.2K_0402_5%  [R_0402]  109.02 1.66 0 bottom
RH535  10K_0402_5%  [R_0402]  76.72 19.12 180 top
RH536  1K_0402_5%  [R_0402]  113.98 6.37 270 top
RH537  10K_0402_5%  [R_0402]  70.88 11.88 180 bottom
RH538  10K_0402_5%  [R_0402]  71.87 11.88 0 bottom
RH539  13_0402_5%  [R_0402]  102.5 11.91 0 bottom
RH540  0_0402_5%  [R0402_0OHM]  132.78 97.75 270 bottom
RH541  0_0402_5%  [R0402_0OHM]  135.51 97.75 270 bottom
RH542  0_0402_5%  [R0402_0OHM]  130.54 94.59 90 bottom
RH543  0_0402_5%  [R0402_0OHM]  128.89 82.32 270 bottom
RH544  10K_0402_5%  [R_0402]  109.02 5.28 0 top
RH545  10K_0402_5%  [R_0402]  112.95 5.53 0 bottom
RH546  10K_0402_5%  [R_0402]  82.92 10.3 0 top
RH547  10K_0402_5%  [R_0402]  70.54 4.63 0 bottom
RH548  10K_0402_5%  [R_0402]  71.45 2.46 180 bottom
RH549  10K_0402_5%  [R_0402]  71.45 5.52 180 bottom
RH550  10K_0402_5%  [R_0402]  70.94 10.63 180 top
RH551  10K_0402_5%  [R_0402]  69.97 11.88 0 top
RH552  10K_0402_5%  [R_0402]  70.88 13.15 180 bottom
RH553  10K_0402_5%  [R_0402]  69.97 15.44 0 bottom
RH554  10K_0402_5%  [R_0402]  76.02 15.38 180 top
RH555  10K_0402_5%  [R_0402]  72.72 15.44 180 bottom
RH556  10K_0402_5%  [R_0402]  70.09 8.78 0 bottom
RH557  10K_0402_5%  [R_0402]  67.17 9.66 0 top
RH558  10K_0402_5%  [R_0402]  91.19 4.23 90 top
RH561  49.9K_0402_1%  [R_0402]  68.11 11.5 180 top
RH562  49.9K_0402_1%  [R_0402]  68.11 12.52 180 top
RH563  10K_0402_5%  [R_0402]  75.11 8.07 0 top
RH564  100K_0402_5%  [R_0402]  79.55 6.42 0 top
RH565  100K_0402_5%  [R_0402]  81.33 6.42 0 top
RH566  100K_0402_5%  [R_0402]  80.07 7.87 90 top
RH567  100K_0402_5%  [R_0402]  78.82 8.54 180 top
RH568  100K_0402_5%  [R_0402]  60.39 2.47 90 bottom
RH569  100K_0402_5%  [R_0402]  61.41 2.47 90 bottom
RH570  49.9_0402_1%  [R_0402]  130.67 78.8 90 bottom
RH571  8.2K_0402_5%  [R_0402]  104.95 5.22 0 top
RH572  100K_0402_5%  [R_0402]  60.57 2.61 0 top
RH573  1K_0402_5%  [R_0402]  69.72 5.42 270 top
RH576  0_0402_5%  [R0402_0OHM]  70.79 3.31 0 top
RH577  0_0402_5%  [R0402_0OHM]  65.93 3.02 0 top
RH578  0_0402_5%  [R0402_0OHM]  66.61 2.08 0 top
RH579  0_0402_5%  [R0402_0OHM]  68.4 1.71 0 top
RH580  0_0402_5%  [R0402_0OHM]  95.51 14.36 90 top
RH581  0_0402_5%  [R0402_0OHM]  98.98 12.45 180 top
RH582  0_0603_5%  [R0603_0OHM]  81.98 31 180 top
RH583  0_0603_5%  [R0603_0OHM]  105.92 15.12 270 top
RH584  0_0603_5%  [R0603_0OHM]  101.79 15.38 0 top
RH585  0_0603_5%  [R0603_0OHM]  60.33 7.31 270 top
RH586  0_0402_5%  [R0402_0OHM]  60.61 10.27 0 bottom
RH587  0_0402_5%  [R_0402]  59.77 9.71 180 bottom
RI4  100K_0402_5%  [R_0402]  28.32 92.03 270 top
RI5  100K_0402_5%  [R_0402]  28.32 88.96 90 top
RI6  33K_0402_1%  [R_0402]  22.3 90.43 180 top
RI7  22.1K_0402_1%  [R_0402]  22.3 89.42 180 top
RI8  10K_0402_5%  [R_0402]  27.64 82.46 180 top
RI9  100K_0402_5%  [R_0402]  325.63 59.88 90 bottom
RI10  100K_0402_5%  [R_0402]  325.63 59.01 270 bottom
RI11  33K_0402_1%  [R_0402]  334.95 62.47 0 bottom
RI12  22.1K_0402_1%  [R_0402]  334.95 61.58 0 bottom
RI13  10K_0402_5%  [R_0402]  322.82 49.35 0 top
RI14  0_0805_5%  [R0805_0OHM]  325.21 35.63 180 bottom
RI15  10K_0402_5%  [R_0402]  323.33 30.68 0 bottom
RI16  0_0402_5%  [R_0402]  323.33 32.46 0 bottom
RI17  10K_0402_5%  [R_0402]  315.93 30.87 180 bottom
RI18  0_0402_5%  [R_0402]  315.93 32.65 180 bottom
RI19  4.7K_0402_5%  [R_0402]  323.33 31.57 0 bottom
RI20  4.7K_0402_5%  [R_0402]  323.33 29.79 0 bottom
RI21  4.7K_0402_5%  [R_0402]  315.93 31.76 180 bottom
RI22  4.7K_0402_5%  [R_0402]  315.66 35.75 90 bottom
RI23  4.99K_0402_1%  [R_0402]  318.14 36.13 90 bottom
RI24  4.7K_0402_5%  [R_0402]  323.33 33.35 0 bottom
RI25  0_0402_5%  [R0402_0OHM]  317.5 28.66 270 bottom
RI26  1M_0402_5%  [R_0402]  27.43 86.67 90 top
RI27  1M_0402_5%  [R_0402]  323.03 53.53 90 top
RI28  0_0402_5%  [R_0402]  323.79 50.67 90 top
RI30  100K_0402_5%  [R_0402]  321.04 43 0 top
RI31  100K_0402_5%  [R_0402]  321.31 44 90 top
RI32  0_0402_5%  [R0402_0OHM]  323.72 47.37 90 top
RI33  0_0402_5%  [R0402_0OHM]  322.45 47.37 90 top
RI34  0_0402_5%  [R_0402]  323.55 46.43 180 top
RI35  0_0402_5%  [R_0402]  324.74 44 90 top
RI36  0_0402_5%  [R0402_0OHM]  316.92 34.17 0 top
RI37  0_0402_5%  [R0402_0OHM]  329.85 72.78 0 top
RI38  0_0402_5%  [R0402_0OHM]  329.85 71.81 0 top
RI39  0_0402_5%  [R0402_0OHM]  329.85 73.72 0 top
RI40  0_0402_5%  [R0402_0OHM]  329.79 74.68 0 top
RI41  0_0402_5%  [R0402_0OHM]  22.56 104.02 180 top
RI42  0_0402_5%  [R0402_0OHM]  22.56 105.04 180 top
RI43  0_0402_5%  [R0402_0OHM]  22.56 103.13 180 top
RI44  0_0402_5%  [R0402_0OHM]  22.56 102.12 180 top
RL1  820_0402_5%  [R_0402]  344.22 101.35 0 top
RL2  820_0402_5%  [R_0402]  344.22 102.37 0 top
RL3  820_0402_5%  [R_0402]  344.22 103.39 0 top
RL4  820_0402_5%  [R_0402]  344.22 104.4 0 top
RL5  820_0402_5%  [R_0402]  344.22 105.29 0 top
RN1  0_0402_5%  [R_0402]  341.26 100.15 180 top
RN33  100K_0402_5%  [R_0402]  339.35 104.61 270 top
RN34  0_0603_5%  [R0603_0OHM]  334.46 100.66 180 top
RP1  2.2K_8P4R_5%  [RP_0804_8P4R]  100.71 8 0 top
RP2  10K_0804_8P4R_5%  [RP_0804_8P4R]  67.24 6.58 0 top
RP4  33_0804_8P4R_5%  [RP_0804_8P4R]  67.82 1.99 0 bottom
RP8  10K_0804_8P4R_5%  [RP_0804_8P4R]  72.2 18.86 180 bottom
RP15  33_8P4R_5%  [RP_0804_8P4R]  64.26 8 0 top
RP19  100K_0804_8P4R_5%  [RP_0804_8P4R]  291.03 7.64 180 top
RP20  10K_8P4R_5%  [RP_0804_8P4R]  311.71 28.84 270 top
RP22  10K_0804_8P4R_5%  [RP_0804_8P4R]  72.96 2.03 0 bottom
RP23  10K_0804_8P4R_5%  [RP_0804_8P4R]  72.96 4.97 0 bottom
RP24  10K_1206_10P8R_5%  [RP_1206_10P8R]  342.34 101.9 90 top
RPH13  2.2K_8P4R_5%  [RP_0804_8P4R]  216.08 64.85 270 top
RPH15  2.2K_8P4R_5%  [RP_0804_8P4R]  212.79 66.24 270 top
RPH32  10K_0804_8P4R_5%  [RP_0804_8P4R]  207.19 54.55 90 bottom
RPH34  10K_0804_8P4R_5%  [RP_0804_8P4R]  216.96 58.92 0 top
RR1  10K_0402_5%  [R_0402]  339.17 33.09 180 bottom
RR2  0_0402_5%  [R0402_0OHM]  329.52 37.6 180 bottom
RR3  0_0402_5%  [R0402_0OHM]  329.52 38.49 180 bottom
RR4  0_0402_5%  [R0402_0OHM]  330.33 39.81 90 bottom
RR5  0_0402_5%  [R0402_0OHM]  332.87 39.81 90 bottom
RR6  6.2K_0402_1%  [R_0402]  330.92 31.07 90 bottom
RR7  0_0402_5%  [R0402_0OHM]  333.76 39.81 90 bottom
RR8  0_0402_5%  [R0402_0OHM]  334.65 39.81 90 bottom
RR9  10K_0402_5%  [R_0402]  338.25 33.98 0 bottom
RR10  0_0402_5%  [R0402_0OHM]  337.31 33.08 90 bottom
RT1  3.01K_0402_1%  [R_0402]  28.04 38.41 90 top
RT2  14K_0402_1%  [R_0402]  29.4 42.91 0 top
RT3  100_0201_1%  [R_0201]  25.15 47.93 270 top
RT4  100_0201_1%  [R_0201]  34.39 43.44 180 bottom
RT5  14K_0402_1%  [R_0402]  31.37 35.12 90 top
RT6  10K_0201_5%  [R_0201]  34.39 43.44 180 top
RT7  10K_0201_5%  [R_0201]  34.39 45.44 180 top
RT8  10K_0201_5%  [R_0201]  34.39 44.87 180 top
RT9  10K_0201_5%  [R_0201]  34.39 44.08 180 top
RT10  4.75K_0402_0.5%  [R_0402]  25.43 42.27 0 top
RT12  499_0201_1%  [R_0201]  25.31 35.87 270 top
RT15  3.3K_0201_1%  [R_0201]  42.76 28.67 180 bottom
RT16  3.3K_0201_1%  [R_0201]  30.35 31.03 270 bottom
RT17  3.3K_0201_1%  [R_0201]  30.99 31.03 270 bottom
RT18  3.3K_0201_1%  [R_0201]  31.62 31.29 270 bottom
RT21  10K_0201_5%  [R_0201]  34.39 44.08 180 bottom
RT22  10K_0201_5%  [R_0201]  31.94 48.17 270 bottom
RT23  10K_0201_5%  [R_0201]  31.88 48.05 270 top
RT25  10K_0201_5%  [R_0201]  24.58 47.93 270 top
RT33  2.2K_0201_5%  [R_0201]  33.61 48.01 270 bottom
RT34  2.2K_0201_5%  [R_0201]  33.02 48.01 270 bottom
RT35  2.2K_0201_5%  [R_0201]  30.1 48.01 270 bottom
RT36  2.2K_0201_5%  [R_0201]  30.74 48.01 270 bottom
RT37  100K_0201_5%  [R_0201]  31.31 48.01 270 bottom
RT38  100K_0201_5%  [R_0201]  19.99 32.62 0 top
RT39  100K_0201_5%  [R_0201]  24.79 48.03 270 bottom
RT40  100K_0201_5%  [R_0201]  19.99 33.26 0 top
RT41  100K_0201_5%  [R_0201]  33.8 45.88 90 bottom
RT42  100K_0201_5%  [R_0201]  35.52 43.44 0 bottom
RT43  100K_0201_5%  [R_0201]  19.99 33.89 0 top
RT44  1M_0201_1%  [R_0201]  19.65 43.77 0 bottom
RT45  1M_0201_1%  [R_0201]  19.65 44.38 0 bottom
RT46  0_0603_5%  [R_0603]  15.68 42.17 0 bottom
RT107  10K_0201_5%  [R_0201]  33.02 47.99 270 top
RT113  0_0603_5%  [R0603_0OHM]  15.24 33.42 270 top
RT114  0.01_0603_1%  [R_0603]  16.51 32.03 90 top
RT164  499_0201_1%  [R_0201]  24.64 35.34 90 top
RT165  0_0805_5%  [R0805_0OHM]  4.07 34.72 90 top
RT167  10K_0201_5%  [R_0201]  13.62 39.54 180 bottom
RT168  3.3K_0201_1%  [R_0201]  10.42 43.1 270 bottom
RT169  3.3K_0201_1%  [R_0201]  9.78 43.1 270 bottom
RT170  3.3K_0201_1%  [R_0201]  20.19 35.29 270 bottom
RT171  3.3K_0201_1%  [R_0201]  12.57 26.84 270 bottom
RT176  0_0402_5%  [R0402_0OHM]  6.58 33.41 270 bottom
RT177  0_0402_5%  [R0402_0OHM]  7.47 33.41 270 bottom
RT178  0_0402_5%  [R0402_0OHM]  12.93 40.41 0 bottom
RT181  0_0402_5%  [R0402_0OHM]  6.74 43.27 0 bottom
RT182  0_0402_5%  [R0402_0OHM]  8 38.06 270 top
RT183  0_0402_5%  [R_0402]  8.97 35.44 180 top
RT184  0_0402_5%  [R0402_0OHM]  12.55 32.55 90 bottom
RT185  0_0402_5%  [R0402_0OHM]  13.46 32.55 90 bottom
RT186  100K_0201_5%  [R_0201]  3.66 37.59 180 bottom
RT187  100K_0201_5%  [R_0201]  11.05 32.86 90 bottom
RT188  100K_0201_5%  [R_0201]  11.69 32.86 90 bottom
RT189  0_0402_5%  [R_0402]  3.66 36.28 180 bottom
RT190  0_0402_5%  [R0402_0OHM]  13.13 37.35 0 bottom
RT191  15K_0402_1%  [R_0402]  15.95 37.6 180 bottom
RT192  3.3K_0201_1%  [R_0201]  8.43 43.35 270 top
RT193  3.3K_0201_1%  [R_0201]  13.44 43.66 270 top
RT194  100K_0402_5%  [R_0402]  15.55 27.17 270 top
RT195  0_0402_5%  [R0402_0OHM]  17.95 25.05 0 top
RT198  0_0402_5%  [R0402_0OHM]  6.68 38.31 270 top
RT199  0_0402_5%  [R_0402]  5.63 36.53 270 top
RT200  0_0402_5%  [R0402_0OHM]  12.66 44.09 270 top
RT201  0_0402_5%  [R0402_0OHM]  13.46 40.06 90 top
RT202  10K_0201_5%  [R_0201]  24.91 49.6 0 top
RT207  100K_0201_5%  [R_0201]  19.65 44.97 0 bottom
RT208  100K_0201_5%  [R_0201]  19.65 43.19 0 bottom
RT209  100K_0201_5%  [R_0201]  25.39 47.92 270 bottom
RT210  0_0201_5%  [R_0201]  18.2 25.03 180 bottom
RT211  0_0201_5%  [R_0201]  19.18 24.48 90 bottom
RT212  0_0201_5%  [R_0201]  16.38 36.24 270 bottom
RT213  0_0201_5%  [R_0201]  14.44 36.08 0 bottom
RT226  10K_0201_5%  [R_0201]  11.18 37.05 90 top
RT227  10K_0201_5%  [R_0201]  7.88 43.35 270 top
RT228  0_0201_5%  [R_0201]  41.91 31.34 90 bottom
RT229  0_0201_5%  [R_0201]  31.28 29.09 180 bottom
RT230  0_0201_5%  [R_0201]  31.61 27.84 180 bottom
RT231  0_0201_5%  [R_0201]  41.91 30.02 270 bottom
RT232  0_0201_5%  [R_0201]  10.92 33.57 270 top
RT233  0_0201_5%  [R_0201]  10.48 32.71 90 bottom
RT240  0_0402_5%  [R0402_0OHM]  14.48 28.38 90 top
RT241  0_0603_5%  [R0603_0OHM]  17.08 40.78 180 bottom
RT242  0_0402_5%  [R_0402]  32.26 35.87 90 top
RT243  0_0402_5%  [R0402_0OHM]  13.34 27.01 270 bottom
RT244  0_0402_5%  [R0402_0OHM]  25.66 51.27 270 top
RT245  0_0201_5%  [R_0201]  3.66 38.19 180 bottom
RT246  0_0402_5%  [R0402_0OHM]  13.72 30.16 90 bottom
RV10  0_0402_5%  [R0402_0OHM]  196.69 60.23 90 top
RV29  10K_0402_5%  [R_0402]  196.93 53.12 90 top
RV45  100K_0402_5%  [R_0402]  201.55 45.45 90 top
RV50  10K_0402_5%  [R_0402]  196.9 52.22 0 top
RV107  10K_0402_5%  [R_0402]  54.28 27.19 0 top
RV109  100K_0402_5%  [R_0402]  51.42 27.19 0 top
RV110  0_0402_5%  [R0402_0OHM]  63.96 28.52 180 top
RV113  0_0402_5%  [R0402_0OHM]  58.68 24.95 90 top
RV114  100K_0402_5%  [R_0402]  59.56 24.95 90 top
RV119  1M_0402_5%  [R_0402]  47.68 20.58 0 bottom
RV120  100K_0402_5%  [R_0402]  49.58 21.92 0 bottom
RV121  10K_0402_5%  [R_0402]  18.09 78.94 0 top
RV122  1M_0402_5%  [R_0402]  17.12 87.05 0 bottom
RV123  20K_0402_5%  [R_0402]  15.8 88.99 270 bottom
RV124  2.2K_0402_5%  [R_0402]  18.54 92.03 270 bottom
RV125  2.2K_0402_5%  [R_0402]  14.73 92.03 270 bottom
RV135  220K_0402_5%  [R_0402]  54.23 22.16 90 bottom
RV181  100K_0402_5%  [R_0402]  199.25 57.92 0 bottom
RV187  10K_0402_5%  [R_0402]  199.59 50.17 180 top
RV208  0_0402_5%  [R_0402]  197.83 53.12 90 top
RV209  100K_0402_5%  [R_0402]  211.07 59.5 90 bottom
RV286  200_0402_1%  [R_0402]  202.76 86.14 180 top
RV290  2.49K_0402_1%  [R_0402]  194.2 96.02 180 bottom
RV299  2.2K_0402_5%  [R_0402]  211.99 59.5 90 bottom
RV300  2.2K_0402_5%  [R_0402]  214.87 59.5 90 bottom
RV301  10K_0402_1%  [R_0402]  219.01 60.41 270 bottom
RV302  4.99K_0402_1%  [R_0402]  228.92 63.59 270 top
RV303  4.99K_0402_1%  [R_0402]  234.72 63.59 270 top
RV304  34.8K_0402_1%  [R_0402]  224.3 63.19 180 top
RV305  15K_0402_1%  [R_0402]  224.3 61.92 180 top
RV306  30.1K_0402_1%  [R_0402]  229.87 63.59 270 top
RV307  10K_0402_1%  [R_0402]  232.55 63.59 270 top
RV308  49.9K_0402_1%  [R_0402]  219.97 60.41 270 bottom
RV309  45.3K_0402_1%  [R_0402]  218.06 60.41 270 bottom
RV310  4.99K_0402_1%  [R_0402]  228.03 62.67 90 top
RV311  4.99K_0402_1%  [R_0402]  233.44 62.67 90 top
RV312  4.99K_0402_1%  [R_0402]  226.26 63.19 180 top
RV313  4.99K_0402_1%  [R_0402]  226.26 61.92 180 top
RV314  34.8K_0402_1%  [R_0402]  230.77 62.67 90 top
RV315  4.99K_0402_1%  [R_0402]  231.66 62.67 90 top
RV316  10K_0402_1%  [R_0402]  220.16 57.34 90 bottom
RV318  40.2K_0402_1%  [R_0402]  220.8 59.64 270 top
RV319  2.2K_0402_5%  [R_0402]  212.95 59.5 90 bottom
RV320  10K_0402_5%  [R_0402]  195.07 61.35 0 bottom
RV323  10K_0402_5%  [R_0402]  195.99 62.24 180 bottom
RV324  10K_0402_5%  [R_0402]  193.37 62.29 270 bottom
RV325  1.8K_0402_5%  [R_0402]  212.34 62.95 270 top
RV326  1.8K_0402_5%  [R_0402]  211.44 63.83 0 top
RV327  40.2_0402_1%  [R_0402]  218.62 73.22 180 top
RV328  40.2_0402_1%  [R_0402]  216.76 71.9 180 top
RV329  60.4_0402_1%  [R_0402]  216.76 71.01 180 top
RV330  100_0402_1%  [R_0402]  226.33 57.74 270 top
RV331  2.2K_0402_5%  [R_0402]  213.87 59.5 90 bottom
RV332  100_0402_1%  [R_0402]  225.44 57.74 270 top
RV338  10K_0402_5%  [R_0402]  200.95 97.85 0 top
RV339  10K_0402_5%  [R_0402]  217.35 100.05 90 top
RV340  10K_0402_5%  [R_0402]  200.28 99.97 0 top
RV341  10K_0402_5%  [R_0402]  218.24 98.22 270 bottom
RV342  1.1K_0402_1%  [R_0402]  219.65 84.82 0 top
RV343  1.1K_0402_1%  [R_0402]  220.7 85.68 90 top
RV344  60.4_0402_1%  [R_0402]  214.03 86.52 270 top
RV345  60.4_0402_1%  [R_0402]  209.78 85.34 90 top
RV346  60.4_0402_1%  [R_0402]  220.56 73.61 0 top
RV347  60.4_0402_1%  [R_0402]  220.82 79.97 0 top
RV348  80.6_0402_1%  [R_0402]  219.28 112.09 180 top
RV352  1K_0402_1%  [R_0402]  219.15 97.3 90 bottom
RV353  1K_0402_1%  [R_0402]  221.56 106.05 180 top
RV354  121_0402_1%  [R_0402]  217.11 114.26 270 bottom
RV355  1.33K_0402_1%  [R_0402]  224.02 106.47 0 top
RV356  1.33K_0402_1%  [R_0402]  217.49 113.11 180 top
RV357  931_0402_1%  [R_0402]  226.71 101.29 270 top
RV358  549_0402_1%  [R_0402]  224.9 101.29 0 top
RV359  931_0402_1%  [R_0402]  225.92 99.45 0 top
RV360  549_0402_1%  [R_0402]  224.91 100.36 0 top
RV361  80.6_0402_1%  [R_0402]  200.42 112.09 180 top
RV363  1K_0402_1%  [R_0402]  200.2 97.16 0 bottom
RV365  121_0402_1%  [R_0402]  199.9 114.26 270 bottom
RV366  1K_0402_1%  [R_0402]  198.61 112.93 270 top
RV368  1.33K_0402_1%  [R_0402]  207.38 109.17 0 top
RV369  1.33K_0402_1%  [R_0402]  203.14 112.92 270 top
RV370  931_0402_1%  [R_0402]  207.38 110.05 0 top
RV371  549_0402_1%  [R_0402]  208.29 110.94 180 top
RV372  931_0402_1%  [R_0402]  209.17 110.98 270 top
RV373  549_0402_1%  [R_0402]  208.27 111.83 0 top
RV374  80.6_0402_1%  [R_0402]  247.14 72.48 270 top
RV378  1K_0402_1%  [R_0402]  233.16 70.43 90 bottom
RV379  1K_0402_1%  [R_0402]  244.69 73.77 180 top
RV380  121_0402_1%  [R_0402]  248.29 63.75 90 bottom
RV381  1.33K_0402_1%  [R_0402]  242.14 64.8 180 top
RV382  1.33K_0402_1%  [R_0402]  247.14 65.41 90 top
RV383  931_0402_1%  [R_0402]  243.96 64.63 270 top
RV384  549_0402_1%  [R_0402]  242.73 80.2 270 top
RV385  931_0402_1%  [R_0402]  246.25 65.41 180 top
RV386  549_0402_1%  [R_0402]  248.29 67.23 270 top
RV387  80.6_0402_1%  [R_0402]  247.08 89.34 90 top
RV389  1K_0402_1%  [R_0402]  233.13 93.63 270 bottom
RV391  121_0402_1%  [R_0402]  245.08 100.02 0 bottom
RV392  1K_0402_1%  [R_0402]  245.21 91.02 180 top
RV394  1.33K_0402_1%  [R_0402]  244.55 99.59 90 top
RV395  1.33K_0402_1%  [R_0402]  247.52 87.73 0 top
RV396  931_0402_1%  [R_0402]  246.52 99.54 270 top
RV397  549_0402_1%  [R_0402]  245.55 100.43 0 top
RV398  931_0402_1%  [R_0402]  247.51 85.48 0 top
RV399  549_0402_1%  [R_0402]  247.56 83.69 90 top
RV409  10K_0402_5%  [R_0402]  233.34 88.2 270 top
RV410  10K_0402_5%  [R_0402]  233.16 69.49 270 bottom
RV414  10K_0402_5%  [R_0402]  234.26 89.96 270 top
RV418  10K_0402_5%  [R_0402]  233.16 72.26 90 bottom
RV479  10K_0402_5%  [R_0402]  205.59 69.87 270 top
RV501  10K_0402_5%  [R_0402]  227.22 56.83 90 top
RV510  0_0402_5%  [R0402_0OHM]  225.4 96.82 270 top
RV511  0_0805_5%  [R0805_0OHM]  203.2 58.34 90 bottom
RV512  475_0402_1%  [R_0402]  21.9 83.96 0 top
RV513  475_0402_1%  [R_0402]  21.9 84.84 0 top
RV514  475_0402_1%  [R_0402]  21.9 80.02 0 top
RV515  475_0402_1%  [R_0402]  21.9 80.91 0 top
RV516  475_0402_1%  [R_0402]  21.9 81.86 0 top
RV517  475_0402_1%  [R_0402]  21.9 82.75 0 top
RV518  475_0402_1%  [R_0402]  21.9 85.73 0 top
RV519  475_0402_1%  [R_0402]  21.9 86.62 0 top
RV520  0_0402_5%  [R0402_0OHM]  63.25 24.44 90 bottom
RV521  0_0402_5%  [R0402_0OHM]  64.26 24.44 90 bottom
RV522  0_0402_5%  [R0402_0OHM]  65.15 24.44 90 bottom
RV523  0_0402_5%  [R0402_0OHM]  66.17 24.44 90 bottom
RV524  0_0402_5%  [R0402_0OHM]  69.47 24.44 90 bottom
RV525  0_0402_5%  [R0402_0OHM]  70.49 24.44 90 bottom
RV526  0_0402_5%  [R0402_0OHM]  71.38 24.44 90 bottom
RV527  0_0402_5%  [R0402_0OHM]  72.39 24.44 90 bottom
RV528  0_0402_5%  [R0402_0OHM]  62.36 24.44 90 bottom
RV529  0_0402_5%  [R0402_0OHM]  61.34 24.44 90 bottom
RV530  8.2_0402_1%  [R_0402]  20.02 86.67 180 top
RV531  8.2_0402_1%  [R_0402]  20.02 85.78 180 top
RV532  8.2_0402_1%  [R_0402]  20.02 82.8 180 top
RV533  8.2_0402_1%  [R_0402]  20.02 81.91 180 top
RV534  8.2_0402_1%  [R_0402]  20.02 80.83 180 top
RV535  8.2_0402_1%  [R_0402]  20.02 79.94 180 top
RV536  8.2_0402_1%  [R_0402]  20.02 84.9 180 top
RV537  8.2_0402_1%  [R_0402]  20.02 84.01 180 top
RV538  150_0402_5%  [R_0402]  17.78 86.7 270 top
RV539  150_0402_5%  [R_0402]  17.78 82.83 270 top
RV540  150_0402_5%  [R_0402]  17.78 80.86 270 top
RV541  150_0402_5%  [R_0402]  17.78 84.92 270 top
RV542  10K_0402_5%  [R_0402]  219.76 62.28 0 top
RV543  100K_0402_5%  [R_0402]  219.76 63.17 0 top
RV544  100K_0402_5%  [R_0402]  219.76 61.39 0 top
RV545  2.2K_0402_5%  [R_0402]  71.12 26.63 270 top
RV546  2.2K_0402_5%  [R_0402]  65.74 27.31 180 top
RV547  0_0402_5%  [R0402_0OHM]  70.23 26.63 270 top
RV548  0_0402_5%  [R_0402]  70.28 24.65 0 top
RV549  0_0402_5%  [R_0402]  63.96 27.31 180 top
RZ8  10_0402_1%  [R_0402]  238.63 101.41 90 top
RZ9  1_0402_5%  [R_0402]  235.71 105.75 270 top
RZ10  1_0402_5%  [R_0402]  202.17 56.14 0 top
RZ11  100_0603_5%  [R_0603]  204.41 50.49 90 top
RZ12  100K_0402_5%  [R_0402]  236.86 105.75 270 top
RZ13  0_0603_5%  [R0603_0OHM]  310.2 32.39 180 top
RZ15  0_0603_5%  [R0603_0OHM]  312.29 37.03 180 top
RZ18  0_0603_5%  [R0603_0OHM]  58.74 2.99 90 top
RZ26  0_0603_5%  [R0603_0OHM]  340.42 44.08 90 bottom
RZ28  0_0603_5%  [R0603_0OHM]  344.43 37.35 180 bottom
RZ32  100K_0402_5%  [R_0402]  225.35 9.28 270 top
RZ34  0_0805_5%  [R0805_0OHM]  239.02 6.97 90 top
RZ35  0_0603_5%  [R0603_0OHM]  44.51 29.35 0 top
RZ36  0_0805_5%  [R0805_0OHM]  243.52 7.03 90 top
RZ37  0_0603_5%  [R0603_0OHM]  44.39 25.8 0 top
RZ38  100K_0402_5%  [R_0402]  345.56 42.68 0 bottom
RZ39  100K_0402_5%  [R_0402]  345.58 43.81 0 bottom
RZ40  100K_0402_5%  [R_0402]  39.28 28.7 180 top
